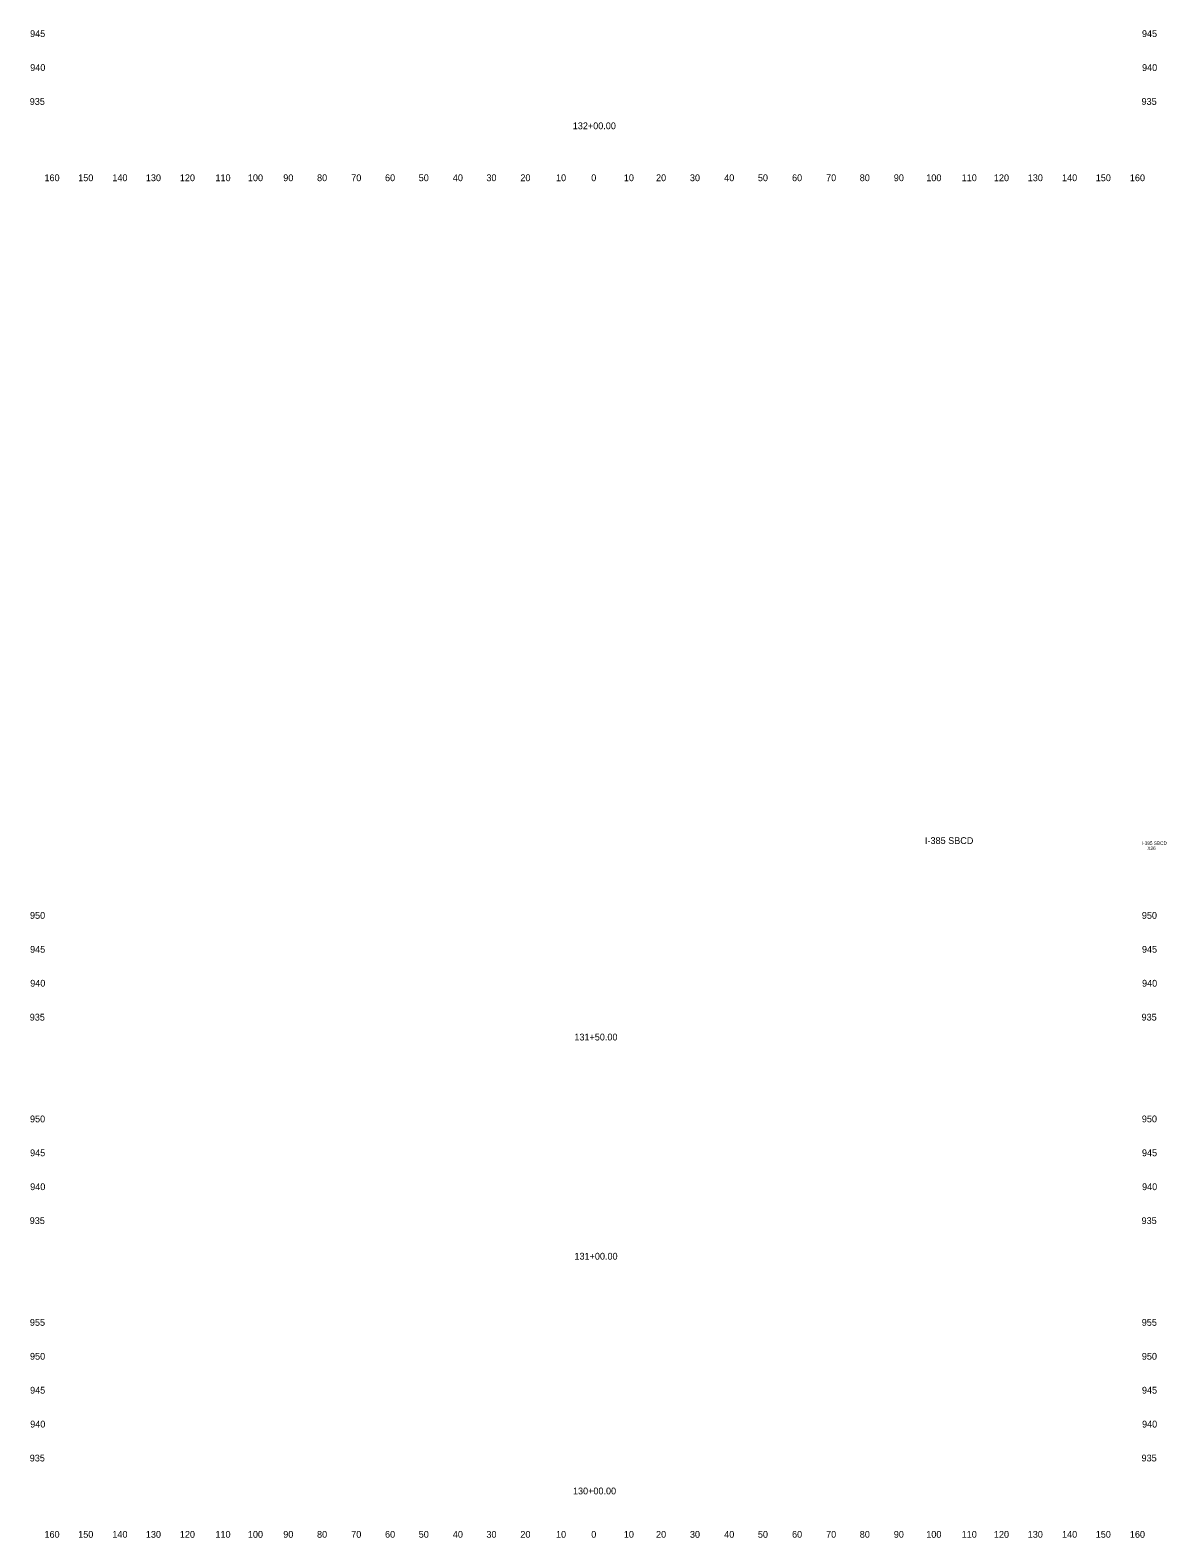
# Model space of a CAD drawing. Extents: x 4994 to 6876, y 4997 to 8804.
# Drawn here: x 6023.9 to 6358.7, y 6997.5 to 7442 of the extents above; entities that cross this region are included whole.
import ezdxf

# ---------------------------------------------------------------- set-up
doc = ezdxf.new("R2010")
doc.units = 0
for name, color, linetype in [('RD_SHT_ID', 7, 'Continuous'), ('RD_XS_TX_Offset', 7, 'Continuous'), ('RD_XS_TX_Station', 7, 'Continuous')]:
    doc.layers.add(name, color=color, linetype=linetype)

msp = doc.modelspace()

# ---------------------------------------------------------------- texts
at = {"layer": 'RD_SHT_ID'}
for s, height, p in [('I-385 SBCD', 2, (6287.69, 7202.06)), ('I-385 SBCD', 1, (6351.63, 7201.8)), ('X26', 1, (6353.26, 7200.3))]:
    msp.add_text(s, height=height, dxfattribs=at).set_placement(p)
at = {"layer": 'RD_XS_TX_Offset'}
for s, p in [('945', (6023.86, 7440)), ('945', (6351.66, 7440)), ('940', (6023.89, 7430)), ('940', (6351.69, 7430)), ('935', (6023.75, 7420)), ('935', (6351.55, 7420)), ('160', (6028.1, 7397.5)), ('150', (6038.04, 7397.5)), ('140', (6048.1, 7397.5)), ('130', (6057.99, 7397.5)), ('120', (6068.01, 7397.5)), ('110', (6078.51, 7397.5)), ('100', (6088.07, 7397.5)), ('90', (6098.5, 7397.5)), ('80', (6108.46, 7397.5)), ('70', (6118.54, 7397.5)), ('60', (6128.5, 7397.5)), ('50', (6138.43, 7397.5)), ('40', (6148.5, 7397.5)), ('30', (6158.39, 7397.5)), ('20', (6168.4, 7397.5)), ('10', (6178.91, 7397.5)), ('0', (6189.3, 7397.5)), ('0', (6189.3, 7397.5)), ('10', (6198.91, 7397.5)), ('20', (6208.4, 7397.5)), ('30', (6218.39, 7397.5)), ('40', (6228.5, 7397.5)), ('50', (6238.43, 7397.5)), ('60', (6248.5, 7397.5)), ('70', (6258.54, 7397.5)), ('80', (6268.46, 7397.5)), ('90', (6278.5, 7397.5)), ('100', (6288.07, 7397.5)), ('110', (6298.51, 7397.5)), ('120', (6308.01, 7397.5)), ('130', (6317.99, 7397.5)), ('140', (6328.1, 7397.5)), ('150', (6338.04, 7397.5)), ('160', (6348.1, 7397.5)), ('950', (6023.83, 7180)), ('950', (6351.63, 7180)), ('945', (6023.86, 7170)), ('945', (6351.66, 7170)), ('940', (6023.89, 7160)), ('940', (6351.69, 7160)), ('935', (6023.75, 7150)), ('935', (6351.55, 7150)), ('950', (6023.83, 7120)), ('950', (6351.63, 7120)), ('945', (6023.86, 7110)), ('945', (6351.66, 7110)), ('940', (6023.89, 7100)), ('940', (6351.69, 7100)), ('935', (6023.75, 7090)), ('935', (6351.55, 7090)), ('955', (6023.8, 7060)), ('955', (6351.6, 7060)), ('950', (6023.83, 7050)), ('950', (6351.63, 7050)), ('945', (6023.86, 7040)), ('945', (6351.66, 7040)), ('940', (6023.89, 7030)), ('940', (6351.69, 7030)), ('935', (6023.75, 7020)), ('935', (6351.55, 7020)), ('160', (6028.1, 6997.5)), ('150', (6038.04, 6997.5)), ('140', (6048.1, 6997.5)), ('130', (6057.99, 6997.5)), ('120', (6068.01, 6997.5)), ('110', (6078.51, 6997.5)), ('100', (6088.07, 6997.5)), ('90', (6098.5, 6997.5)), ('80', (6108.46, 6997.5)), ('70', (6118.54, 6997.5)), ('60', (6128.5, 6997.5)), ('50', (6138.43, 6997.5)), ('40', (6148.5, 6997.5)), ('30', (6158.39, 6997.5)), ('20', (6168.4, 6997.5)), ('10', (6178.91, 6997.5)), ('0', (6189.3, 6997.5)), ('0', (6189.3, 6997.5)), ('10', (6198.91, 6997.5)), ('20', (6208.4, 6997.5)), ('30', (6218.39, 6997.5)), ('40', (6228.5, 6997.5)), ('50', (6238.43, 6997.5)), ('60', (6248.5, 6997.5)), ('70', (6258.54, 6997.5)), ('80', (6268.46, 6997.5)), ('90', (6278.5, 6997.5)), ('100', (6288.07, 6997.5)), ('110', (6298.51, 6997.5)), ('120', (6308.01, 6997.5)), ('130', (6317.99, 6997.5)), ('140', (6328.1, 6997.5)), ('150', (6338.04, 6997.5)), ('160', (6348.1, 6997.5))]:
    msp.add_text(s, height=2, dxfattribs=at).set_placement(p)
at = {"layer": 'RD_XS_TX_Station'}
for s, p in [('132+00.00', (6183.85, 7412.82)), ('131+50.00', (6184.32, 7144.13)), ('131+00.00', (6184.35, 7079.51)), ('130+00.00', (6183.91, 7010.3))]:
    msp.add_text(s, height=2, dxfattribs=at).set_placement(p)

doc.saveas('drawing.dxf')
